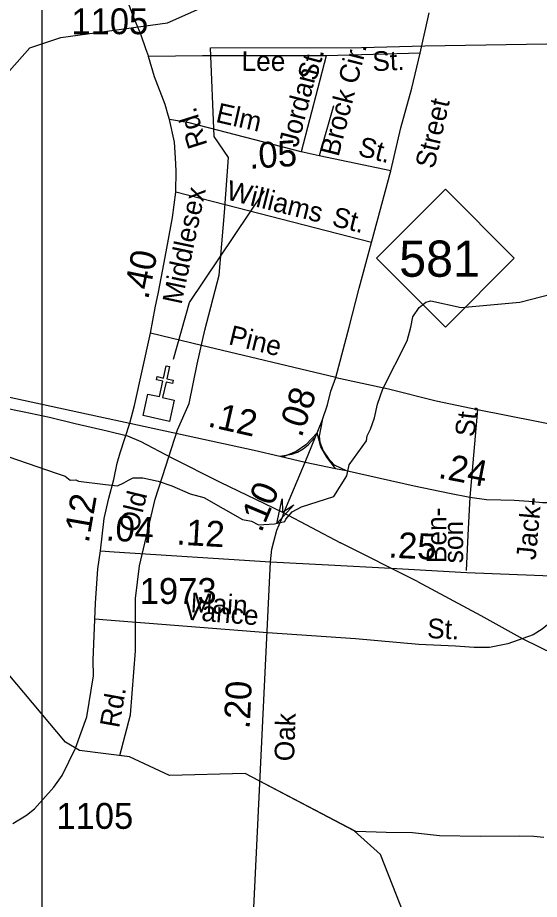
# Model space of a CAD drawing. Extents: x 2220236 to 2384410, y 720751 to 894131.
# Drawn here: x 2259849 to 2262372, y 738060 to 742321 of the extents above; entities that cross this region are included whole.
import ezdxf

# ---------------------------------------------------------------- set-up
doc = ezdxf.new("R2010")
doc.units = 0
for name, color, linetype in [('Exist Boundary Political City Limit New', 7, 'Continuous'), ('Exist Cultural Church CELL', 7, 'Continuous'), ('Exist Hydrographic Creek Single Shore', 7, 'Continuous'), ('Exist Hydrographic Misc Water Feature', 7, 'Continuous'), ('Exist Railroad Mainline', 7, 'Continuous'), ('Exist Road Non-System Type 51', 7, 'Continuous'), ('Exist Road Non-System Type 51 Label', 7, 'Continuous'), ('Exist Road Primary NC Attributed', 7, 'Continuous'), ('Exist Road Primary NC Label', 7, 'Continuous'), ('Exist Road Primary NC Service Mileage Hundredths English Label', 7, 'Continuous'), ('Exist Road Primary NC Shield CELL', 7, 'Continuous'), ('Exist Road Primary NC Shield Number Label', 7, 'Continuous'), ('Exist Road Primary US Attributed', 7, 'Continuous'), ('Exist Road Primary US Mileage Hundredths English Label', 7, 'Continuous'), ('Exist Road Primary US Ramp 1 Lane  Attributed', 7, 'Continuous'), ('Exist Road Primary US Structure RailRoad Attributed CELL', 7, 'Continuous'), ('Exist Road Secondary Mileage Hundredths English Label', 7, 'Continuous'), ('Exist Road Secondary Type 51 Attributed', 7, 'Continuous'), ('Exist Road Secondary Type 51 Label', 7, 'Continuous'), ('Exist Road Secondary Type 51 Number Label', 7, 'Continuous'), ('Map Preparation Boundary City Limit Buffer Line', 7, 'Continuous'), ('Map Preparation Inset Cut Line', 7, 'Continuous')]:
    doc.layers.add(name, color=color, linetype=linetype)

msp = doc.modelspace()

# ---------------------------------------------------------------- linework, layer by layer
at = {"layer": 'Exist Boundary Political City Limit New'}
msp.add_lwpolyline([(2262393.2, 738358.8), (2262345.2, 738364.5), (2262277.2, 738366.1), (2262087.2, 738363.2), (2261889.2, 738366.3), (2261759, 738381.8), (2261631, 738383), (2261484.5, 738387.2), (2260949.2, 738668), (2260583.2, 738659.1), (2260390.2, 738748.4), (2260342.8, 738754.5), (2260394.5, 738951.6), (2260419.8, 739261.4), (2260419.8, 739514.3), (2260438.8, 739672.4), (2260514.5, 739994.8), (2260565, 740152.9), (2260621.8, 740329.9), (2260678.8, 740456.4), (2260716.5, 740646.1), (2260754.5, 740810.4), (2260824, 741076), (2260849.2, 741379.5), (2260868.2, 741645.1), (2260798.8, 741746.2), (2260781, 742174.8), (2261512.5, 742177.4), (2261817.5, 742185.4), (2262801, 742201.3)], dxfattribs=at)
at = {"layer": 'Exist Cultural Church CELL'}
msp.add_lwpolyline([(2260478.8, 740501.9), (2260534.4, 740489.4), (2260551.2, 740563.7), (2260520, 740570.8), (2260523.5, 740586.3), (2260554.7, 740579.3), (2260568, 740637.9), (2260583.6, 740634.4), (2260570.4, 740575.7), (2260601.6, 740568.7), (2260598, 740553.1), (2260566.8, 740560.2), (2260550, 740485.9), (2260606.2, 740473), (2260582.7, 740369.2), (2260455.3, 740398.1)], close=True, dxfattribs=at)
at = {"layer": 'Exist Hydrographic Creek Single Shore'}
for points in [[(2259598, 741827.9), (2259908.2, 742175.9), (2260057.3, 742225.3), (2260573.2, 742296.7), (2261129.3, 742544.4), (2261179.3, 742595.9), (2261333.3, 742996.2), (2261465.4, 743098.3), (2261664.3, 743189.4), (2261905.2, 743243.5), (2261938.3, 743285.4), (2262104.3, 743387), (2262370.3, 743463.5)], [(2259802.2, 740200.3), (2260040.7, 740117.9), (2260079.6, 740104.5), (2260103.4, 740085.4), (2260131.2, 740087), (2260143.1, 740080.7), (2260274.3, 740064.8), (2260331.4, 740058.5), (2260362.3, 740073.5), (2260385.3, 740086.2), (2260407.5, 740097.3), (2260455.1, 740097.3), (2260528.3, 740080.4), (2260594.7, 740058.5), (2260682.7, 740020.4), (2260750.2, 740001.4), (2260936.1, 739895.9), (2260979.2, 739887.5), (2261013.1, 739869.7), (2261091.6, 739874.5), (2261140.8, 739885.6), (2261145.5, 739897.5), (2261176.4, 739932.4), (2261222.4, 739956.9), (2261378.2, 740007.2), (2261441.3, 740106), (2261452.4, 740160), (2261535.7, 740275.8), (2261539.7, 740299.6), (2261554.7, 740332.9), (2261574.6, 740387.6), (2261589.2, 740453.4), (2261614.6, 740528), (2261732, 740759.5), (2261751, 740824.6), (2261760.5, 740874.5), (2261791.1, 740919.7), (2261823.6, 740945.9), (2261847.4, 740952.3), (2261994.2, 740919.5), (2262277.2, 740946.5), (2262584.4, 741025.4)], [(2261833.2, 737695.4), (2261603.2, 738277.4), (2261476.2, 738391.5), (2260949.2, 738668), (2260583.2, 738659.1), (2260390.3, 738748.4), (2260148.3, 738779.6), (2260081.2, 738820.3)]]:
    msp.add_lwpolyline(points, dxfattribs=at)
at = {"layer": 'Exist Hydrographic Misc Water Feature'}
msp.add_lwpolyline([(2260081.2, 738820.3), (2259803.2, 739150.7), (2259668.3, 739350.2), (2259619.9, 739354.7)], dxfattribs=at)
at = {"layer": 'Exist Railroad Mainline'}
msp.add_line((2261782.3, 739596.2), (2261410.6, 739782.6), dxfattribs=at)
for points in [[(2259769.3, 740438.8), (2259881.4, 740415.9), (2260003.6, 740391), (2260127.7, 740360.2), (2260282.1, 740323.7), (2260380.2, 740300.7), (2260444.4, 740273.1), (2260591.2, 740194.6), (2260828.1, 740076.9), (2261130.2, 739930.9), (2261410.6, 739782.6)], [(2261782.3, 739596.2), (2262089.6, 739431.2), (2262292.6, 739319)], [(2262292.6, 739319), (2262591.9, 739171.9), (2262776.5, 739079.7), (2262989.6, 738961.8), (2263094, 738912.9), (2263222.3, 738864), (2263346.6, 738831.3), (2263498.8, 738794.8), (2263609, 738773.7), (2263711.1, 738760.6), (2264043.1, 738737.8), (2264447.2, 738711.7), (2264921.4, 738678.1), (2265321.4, 738655.9), (2265719.3, 738639.7), (2266099.3, 738615.3), (2266235.2, 738612.5), (2266365.4, 738597.6), (2266485.6, 738577), (2266585.7, 738545.9), (2266703.9, 738516.9), (2266814.4, 738474)]]:
    msp.add_lwpolyline(points, dxfattribs=at)
at = {"layer": 'Exist Road Non-System Type 51'}
for p, q in [((2261340.6, 742136.7), (2261220.8, 741671.9)), ((2261795.1, 742148.6), (2261340.6, 742136.7)), ((2261377.1, 741895.5), (2261307, 741652.9)), ((2261307, 741652.9), (2261220.8, 741671.9)), ((2261653.6, 741580), (2261307, 741652.9)), ((2262072.3, 740427.6), (2262035.1, 740003.7))]:
    msp.add_line(p, q, dxfattribs=at)
for points in [[(2260350.5, 742510.2), (2260368.1, 742437.9), (2260405.3, 742334.8), (2260444.8, 742238.3), (2260466.7, 742172.6), (2260482, 742133.1)], [(2261340.6, 742136.7), (2260742.9, 742137.2), (2260482, 742133.1)], [(2261220.8, 741671.9), (2260678.6, 741812.6), (2260583.9, 741828.3)], [(2261560.5, 741234.8), (2260851.8, 741416.2), (2260613.5, 741477.5)], [(2261387.4, 740581.4), (2260737.5, 740736.9), (2260490.8, 740795.6)], [(2261296.8, 740315.4), (2261242.1, 740257.1), (2261196, 740223.6), (2261130.1, 740196.6)], [(2261385.9, 740142.9), (2261343.5, 740197), (2261315.8, 740246.7), (2261296.8, 740315.4)], [(2262035.1, 740003.7), (2262026.3, 739819.5), (2262017.5, 739649.9)], [(2262470.4, 739622.1), (2262456.7, 739518.6), (2262445.2, 739456.4), (2262435.6, 739418.5), (2262411.9, 739386.1), (2262386.1, 739365.9), (2262342.4, 739337.6), (2262218.9, 739294.4), (2262131, 739277.6), (2262057, 739276.9), (2261967, 739283.9), (2261789, 739292.4), (2261482.9, 739319.5), (2261057, 739347.5)], [(2261057, 739347.5), (2260281, 739409.1), (2260224.6, 739413.6)]]:
    msp.add_lwpolyline(points, dxfattribs=at)
at = {"layer": 'Exist Road Primary NC Attributed'}
for points in [[(2261387.4, 740581.4), (2261451.6, 740825.5), (2261499.8, 741014.1), (2261560.5, 741234.8), (2261653.6, 741580), (2261701.6, 741788.4), (2261755.8, 741980.8), (2261795.1, 742148.6), (2261839.2, 742345.1)], [(2261239.8, 740172.1), (2261321.6, 740374.1), (2261347.7, 740450.2), (2261364, 740515.6), (2261387.4, 740581.4)], [(2261072.2, 739690.5), (2261077.5, 739752.2), (2261087.2, 739788.8), (2261102.3, 739843.5), (2261113.4, 739869.7), (2261129.3, 739907.2), (2261136.6, 739927.2), (2261239.8, 740172.1)], [(2261161.5, 735036.6), (2261087, 735593.5), (2261037.3, 736052.5), (2261004.4, 736520.3), (2260982.5, 736866.7), (2260975.2, 737026), (2260962.1, 737232.1), (2260965.7, 737451.4), (2260993.5, 738053.7), (2261072.2, 739690.5)]]:
    msp.add_lwpolyline(points, dxfattribs=at)
at = {"layer": 'Exist Road Primary NC Shield CELL'}
msp.add_lwpolyline([(2261584.8, 741158.6), (2261917.8, 741491.6), (2262250.8, 741158.6), (2261917.8, 740825.6)], close=True, dxfattribs=at)
at = {"layer": 'Exist Road Primary US Attributed'}
for points in [[(2256853.7, 740585.5), (2257480.3, 740701.3), (2257881.8, 740792.2), (2258057.8, 740806.7), (2258208, 740813.6), (2258416.9, 740791.1), (2258760.4, 740722), (2259062.5, 740658.1), (2259467.8, 740565.3), (2259546.7, 740546.3), (2259608.1, 740530.3), (2260241.8, 740393.9), (2260390.9, 740360.6)], [(2260390.9, 740360.6), (2260992.6, 740230.5), (2261117, 740202), (2261239.8, 740172.1)], [(2261239.8, 740172.1), (2261385.9, 740142.9), (2261438.2, 740132.2), (2261767.2, 740058.1), (2261937.2, 740022.7), (2262035.1, 740003.7), (2262116.3, 739993), (2262185.5, 739990.5), (2262249.8, 739989), (2262321.4, 739984.7), (2262386.3, 739977.7), (2262487.9, 739977.3)]]:
    msp.add_lwpolyline(points, dxfattribs=at)
at = {"layer": 'Exist Road Primary US Mileage Hundredths English Label'}
msp.add_lwpolyline([(2260603.4, 740669.9), (2260680.4, 740944.3), (2261042, 741483.6)], dxfattribs=at)
at = {"layer": 'Exist Road Primary US Ramp 1 Lane  Attributed'}
for points in [[(2261321.6, 740374.1), (2261307.3, 740298), (2261310.5, 740270.2), (2261326.3, 740228.2), (2261350.1, 740191.7), (2261380.3, 740160), (2261413.6, 740143.3), (2261438.2, 740132.2)], [(2261117, 740202), (2261175.6, 740210.7), (2261201.8, 740221), (2261230.4, 740236.9), (2261254.2, 740255.9), (2261285.1, 740290.8)]]:
    msp.add_lwpolyline(points, dxfattribs=at)
at = {"layer": 'Exist Road Primary US Structure RailRoad Attributed CELL'}
msp.add_lwpolyline([(2261184.1, 739967.4), (2261102.7, 739876.6), (2261127.8, 739995.9), (2261130.2, 739930.9)], close=True, dxfattribs=at)
at = {"layer": 'Exist Road Secondary Type 51 Attributed'}
for points in [[(2260390.9, 740360.6), (2260414.1, 740446.9), (2260490.8, 740795.6), (2260514.9, 740918.4), (2260530.2, 740995.1), (2260563.1, 741163.9), (2260598.1, 741354.7), (2260613.5, 741477.5), (2260615.7, 741580.5), (2260612.4, 741644.1), (2260608, 741718.7), (2260583.9, 741828.3), (2260577.3, 741850.2), (2260562, 741900.7), (2260511.6, 742034.4), (2260482, 742133.1)], [(2261387.4, 740581.4), (2261642.8, 740527), (2261872.2, 740470), (2262072.3, 740427.6), (2262358.6, 740370.6), (2262504, 740341.3), (2262672.9, 740322.1), (2262844.9, 740305.7), (2262959.8, 740296), (2263301.6, 740287.2), (2263396.6, 740285.8), (2263639.1, 740275.5), (2263918.9, 740276.5), (2264090.7, 740284.5), (2264570.6, 740305.4), (2265395.7, 740332.7), (2265870.1, 740351.9), (2266084.5, 740362.5), (2266279.4, 740366.4), (2266759.4, 740372.8), (2267114.1, 740384.1), (2267238.5, 740385.7), (2267291.5, 740385.7)], [(2260249.6, 739743.7), (2260267.2, 739901.4), (2260289.4, 739999), (2260313.6, 740088.8), (2260329.7, 740167.7), (2260344.3, 740217.4), (2260390.9, 740360.6)], [(2261072.2, 739690.5), (2261352.5, 739676.2), (2261654.1, 739660.5), (2262021.9, 739639.7), (2262470.4, 739622.1), (2262487.9, 739977.3)], [(2259826.2, 738426.3), (2259891.8, 738466.9), (2259931.4, 738497.3), (2260024.4, 738602.2), (2260063.9, 738658.5), (2260128.7, 738791.5), (2260183.1, 738941.4), (2260215.2, 739139.7), (2260214.5, 739215.6), (2260226, 739491.5), (2260236.4, 739657.6), (2260249.6, 739743.7)], [(2260249.6, 739743.7), (2260315.5, 739740), (2261072.2, 739690.5)]]:
    msp.add_lwpolyline(points, dxfattribs=at)
at = {"layer": 'Map Preparation Boundary City Limit Buffer Line'}
msp.add_lwpolyline([(2262393.2, 738358.8), (2262345.2, 738364.5), (2262277.2, 738366.1), (2262087.2, 738363.2), (2261889.2, 738366.3), (2261759, 738381.8), (2261631, 738383), (2261484.5, 738387.2), (2260949.2, 738668), (2260583.2, 738659.1), (2260390.2, 738748.4), (2260342.8, 738754.5), (2260394.5, 738951.6), (2260419.8, 739261.4), (2260419.8, 739514.3), (2260438.8, 739672.4), (2260514.5, 739994.8), (2260565, 740152.9), (2260621.8, 740329.9), (2260678.8, 740456.4), (2260716.5, 740646.1), (2260754.5, 740810.4), (2260824, 741076), (2260849.2, 741379.5), (2260868.2, 741645.1), (2260798.8, 741746.2), (2260781, 742174.8), (2261512.5, 742177.4), (2261817.5, 742185.4), (2262801, 742201.3)], dxfattribs=at)
at = {"layer": 'Map Preparation Inset Cut Line'}
msp.add_lwpolyline([(2259967.8, 744228.7), (2273241.2, 744228.7), (2273241.2, 736157.5), (2259967.8, 736157.5), (2259967.8, 744228.7)], dxfattribs=at)
msp.add_lwpolyline([(2259967.8, 744228.7), (2273241.2, 744228.7), (2273241.2, 736157.5), (2259967.8, 736157.5), (2259967.8, 744228.7)], dxfattribs=at)

# ---------------------------------------------------------------- texts
at = {"layer": 'Exist Road Non-System Type 51 Label'}
for s, rotation, p in [('Lee', 359.7971, (2260931.6, 742064.1)), ('Brock Cir.', 75.6696, (2261400.6, 741645.6)), ('St.', 2.3755, (2261566.4, 742062.3)), ('St.', 75.1909, (2261292.7, 742010.7)), ('Jordan', 75.6696, (2261202.7, 741690.2)), ('Elm', 347.1093, (2260802.7, 741817.9)), ('St.', 345.5297, (2261490.3, 741656)), ('Williams', 346.0018, (2260852.8, 741444.1)), ('St.', 346.0018, (2261364.1, 741316.6)), ('St.', 83.4815, (2262057.6, 740292)), ('Jack-', 84.8412, (2262354, 739697.9)), ('Ben-', 89.969, (2261922.2, 739684.9)), ('son', 89.969, (2262003.1, 739684.1)), ('Vance', 355.4599, (2260651.2, 739412.7)), ('St.', 357.2658, (2261827.5, 739323.4))]:
    msp.add_text(s, height=95, rotation=rotation, dxfattribs=at).set_placement(p)
at = {"layer": 'Exist Road Primary NC Label'}
for s, rotation, p in [('Street', 77.03, (2261863.1, 741586.9)), ('Oak', 87.9913, (2261185.5, 738726.1))]:
    msp.add_text(s, height=95, rotation=rotation, dxfattribs=at).set_placement(p)
at = {"layer": 'Exist Road Primary NC Service Mileage Hundredths English Label'}
for s, rotation, p in [('.08', 71.4507, (2261221.6, 740287.8)), ('.10', 67.1453, (2261027, 739828.2)), ('.20', 87.2486, (2260970.7, 738881.2))]:
    msp.add_text(s, height=125, rotation=rotation, dxfattribs=at).set_placement(p)
at = {"layer": 'Exist Road Primary NC Shield Number Label'}
msp.add_text('581', height=175, dxfattribs=at).set_placement((2261694, 741068.8))
at = {"layer": 'Exist Road Primary US Mileage Hundredths English Label'}
for s, rotation, p in [('.05', 3.6268, (2260971, 741590.3)), ('.12', 347.2372, (2260763.8, 740346.4)), ('.24', 349.0123, (2261878.7, 740097.7))]:
    msp.add_text(s, height=125, rotation=rotation, dxfattribs=at).set_placement(p)
at = {"layer": 'Exist Road Secondary Mileage Hundredths English Label'}
for s, rotation, p in [('.40', 78.5531, (2260480.1, 740955.3)), ('.12', 80.1008, (2260192.3, 739778.9)), ('.04', 356.7291, (2260273, 739795)), ('.12', 356.7291, (2260614.8, 739774.9)), ('.25', 357.3619, (2261639.8, 739711.9))]:
    msp.add_text(s, height=125, rotation=rotation, dxfattribs=at).set_placement(p)
at = {"layer": 'Exist Road Secondary Type 51 Label'}
for s, rotation, p in [('Rd.', 107.4841, (2260767.8, 741706.4)), ('Middlesex', 78.0542, (2260641.3, 740931.4)), ('Pine', 346.3193, (2260864.4, 740743.6)), ('Old', 76.2307, (2260429.5, 739827.3)), ('Main', 356.7291, (2260683.7, 739448.1)), ('Rd.', 79.8622, (2260339.3, 738884.8))]:
    msp.add_text(s, height=95, rotation=rotation, dxfattribs=at).set_placement(p)
at = {"layer": 'Exist Road Secondary Type 51 Number Label'}
for s, p in [('1105', (2260108.9, 742241)), ('1973', (2260439.3, 739487.8)), ('1105', (2260036.2, 738400.8))]:
    msp.add_text(s, height=125, dxfattribs=at).set_placement(p)

doc.saveas('drawing.dxf')
